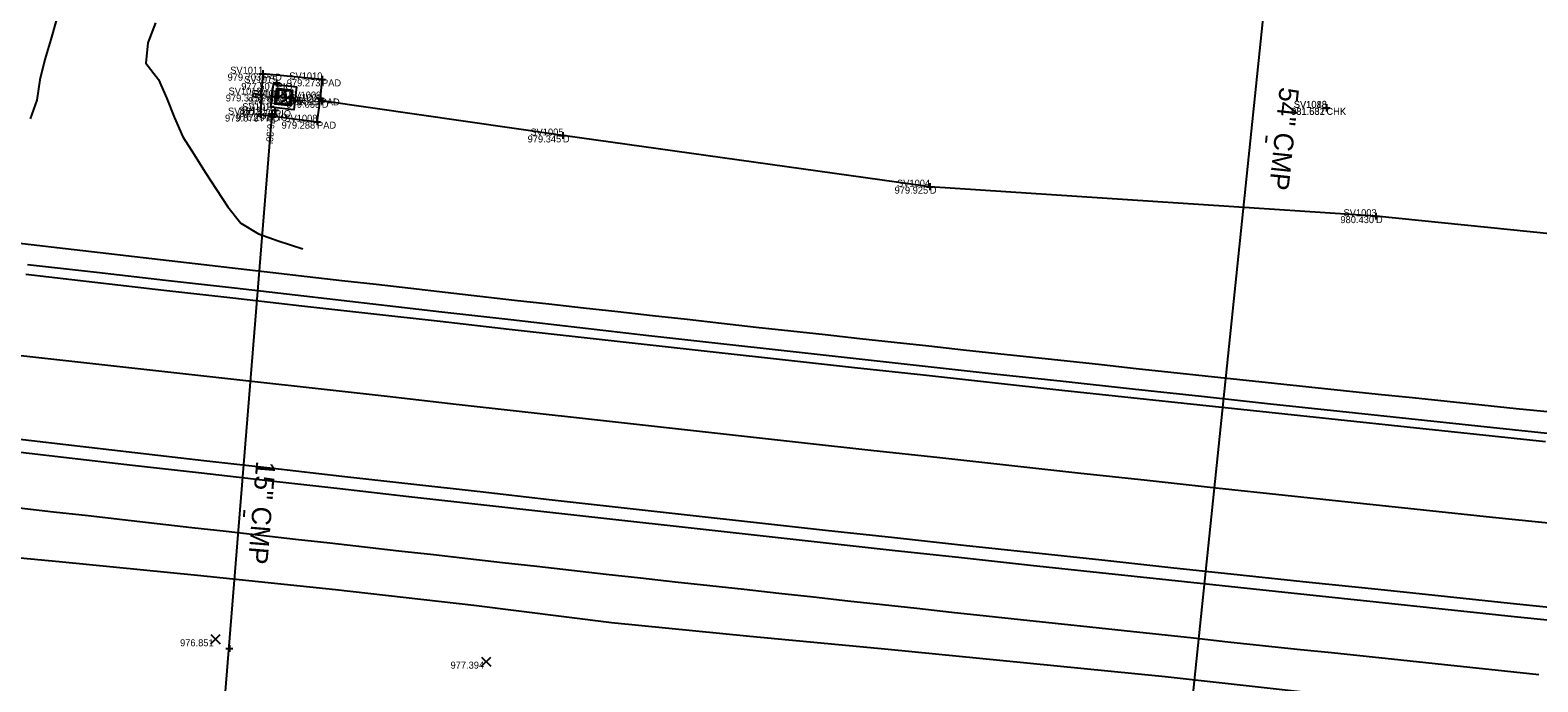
# Model space of a CAD drawing. Extents: x 2065431 to 2068157, y 709104 to 709719.
# Drawn here: x 2067117.5 to 2067334.4, y 709285 to 709378.9 of the extents above; entities that cross this region are included whole.
import ezdxf

# ---------------------------------------------------------------- set-up
doc = ezdxf.new("R2010")
doc.units = 0
for name, color, linetype in [('_CIVIL_CONSTRUCTION', 7, 'Continuous'), ('DR_X_Storm_Sewer', 7, 'Continuous'), ('DR_X_Text', 7, 'Continuous'), ('DT_X_Break_Line', 7, 'Continuous'), ('PM_X_Edge_Line', 7, 'Continuous'), ('PM_X_Lane_Line', 7, 'Continuous'), ('PV_X_EOP', 7, 'Continuous'), ('PV_X_Shoulder_Rumble_Strip', 7, 'Continuous'), ('RD_X_Concrete_Pad', 7, 'Continuous'), ('RS_Raster1', 7, 'Continuous'), ('RW_X_CL', 7, 'Continuous'), ('RW_X_CL_100_Bearings', 7, 'Continuous'), ('RW_X_Fee_WL', 7, 'Continuous'), ('SC_Scratch1', 7, 'Continuous'), ('SV_X_Mon_Cells_Found', 7, 'Continuous'), ('SV_X_Text_Comment', 7, 'Continuous'), ('SV_X_Text_Elevation', 7, 'Continuous'), ('SV_X_Text_Name', 7, 'Continuous')]:
    doc.layers.add(name, color=color, linetype=linetype)

msp = doc.modelspace()

# ---------------------------------------------------------------- linework, layer by layer
at = {"layer": '_CIVIL_CONSTRUCTION'}
for p, q in [((2067152.45, 709371.25), (2067153.45, 709371.25)), ((2067152.95, 709371.75), (2067152.95, 709370.75)), ((2067152.95, 709371.25), (2067152.95, 709371.25)), ((2067151.75, 709366.82), (2067152.75, 709366.82)), ((2067152.21, 709367.33), (2067153.21, 709367.33)), ((2067152.25, 709367.32), (2067152.25, 709366.32)), ((2067152.25, 709366.82), (2067152.25, 709366.82)), ((2067152.71, 709367.83), (2067152.71, 709366.83)), ((2067152.71, 709367.33), (2067152.71, 709367.33))]:
    msp.add_line(p, q, dxfattribs=at)
at = {"layer": 'DR_X_Storm_Sewer'}
for p, q in [((2067313.91, 709564.11), (2067272.26, 709162.87)), ((2067152.25, 709366.82), (2067142.97, 709251.99))]:
    msp.add_line(p, q, dxfattribs=at)
at = {"layer": 'DR_X_Text'}
for p, q in [((2067295.33, 709362.67), (2067295.43, 709363.63)), ((2067148.26, 709308.77), (2067148.34, 709309.74))]:
    msp.add_line(p, q, dxfattribs=at)
at = {"layer": 'DT_X_Break_Line'}
msp.add_lwpolyline([(2067101.73, 709304.2), (2067121.64, 709302.33), (2067141.54, 709300.39), (2067161.43, 709298.3), (2067181.3, 709296.03), (2067201.15, 709293.56), (2067221.05, 709291.6), (2067240.96, 709289.7), (2067260.87, 709287.74), (2067280.77, 709285.77), (2067300.65, 709283.57), (2067320.49, 709281.09), (2067340.37, 709278.88), (2067360.28, 709276.99), (2067380.18, 709275.07), (2067400.09, 709273.09), (2067419.99, 709271.15), (2067439.91, 709269.35), (2067459.83, 709267.56), (2067469.03, 709266.73)], dxfattribs=at)
at = {"layer": 'PM_X_Edge_Line'}
for points in [[(2067116.84, 709343.69), (2067126.78, 709342.56), (2067136.71, 709341.42), (2067146.65, 709340.29), (2067156.58, 709339.16), (2067166.52, 709338.04), (2067176.46, 709336.92), (2067186.39, 709335.8), (2067196.33, 709334.69), (2067206.27, 709333.58), (2067216.21, 709332.48), (2067226.15, 709331.38), (2067236.09, 709330.29), (2067246.03, 709329.2), (2067255.97, 709328.11), (2067265.91, 709327.03), (2067275.85, 709325.96), (2067285.8, 709324.89), (2067295.74, 709323.82), (2067305.68, 709322.76), (2067315.63, 709321.71), (2067325.57, 709320.65), (2067335.52, 709319.61)], [(2067112.67, 709320.32), (2067122.61, 709319.18), (2067132.54, 709318.04), (2067142.48, 709316.9), (2067152.41, 709315.77), (2067162.35, 709314.64), (2067172.28, 709313.52), (2067182.22, 709312.4), (2067192.16, 709311.28), (2067202.1, 709310.17), (2067212.04, 709309.07), (2067221.98, 709307.97), (2067231.92, 709306.87), (2067241.86, 709305.79), (2067251.8, 709304.7), (2067261.74, 709303.63), (2067271.68, 709302.56), (2067281.62, 709301.49), (2067291.57, 709300.43), (2067301.51, 709299.37), (2067311.46, 709298.33), (2067321.4, 709297.28), (2067331.35, 709296.24), (2067341.29, 709295.21)]]:
    msp.add_lwpolyline(points, dxfattribs=at)
at = {"layer": 'PM_X_Lane_Line'}
msp.add_lwpolyline([(2067109.22, 709332.79), (2067119.15, 709331.67), (2067129.09, 709330.56), (2067139.03, 709329.45), (2067148.97, 709328.35), (2067158.91, 709327.25), (2067168.85, 709326.13), (2067178.78, 709325.01), (2067188.72, 709323.89), (2067198.66, 709322.78), (2067208.6, 709321.67), (2067218.54, 709320.57), (2067228.48, 709319.47), (2067238.42, 709318.38), (2067248.36, 709317.29), (2067258.3, 709316.2), (2067268.24, 709315.12), (2067278.18, 709314.04), (2067288.12, 709312.96), (2067298.06, 709311.89), (2067308.01, 709310.83), (2067317.95, 709309.77), (2067327.9, 709308.73), (2067337.84, 709307.7)], dxfattribs=at)
at = {"layer": 'PV_X_EOP'}
for points in [[(2067115.24, 709417.59), (2067117.83, 709416.08), (2067120.3, 709414.41), (2067122.45, 709412.31), (2067123.73, 709409.68), (2067124.59, 709406.81), (2067125.06, 709403.85), (2067125.25, 709400.86), (2067125.25, 709397.86), (2067124.99, 709394.88), (2067124.49, 709391.92), (2067123.95, 709388.98), (2067123.07, 709386.11), (2067122.18, 709383.25), (2067121.29, 709380.38), (2067120.45, 709377.5), (2067119.6, 709374.62), (2067118.87, 709371.71), (2067118.45, 709368.75), (2067117.47, 709366.07)], [(2067135.52, 709379.9), (2067134.43, 709377.04), (2067134.12, 709374.09), (2067135.94, 709371.76), (2067137.15, 709369.02), (2067138.27, 709366.23), (2067139.47, 709363.49), (2067141.08, 709360.95), (2067142.68, 709358.42), (2067144.29, 709355.88), (2067145.95, 709353.39), (2067147.79, 709351.07), (2067150.36, 709349.51), (2067153.17, 709348.49), (2067156.71, 709347.34)], [(2067112.65, 709348.55), (2067117.61, 709347.97), (2067122.58, 709347.4), (2067127.55, 709346.82), (2067132.51, 709346.25), (2067137.48, 709345.68), (2067142.45, 709345.1), (2067147.41, 709344.53), (2067152.38, 709343.96), (2067157.35, 709343.39), (2067162.32, 709342.82), (2067167.28, 709342.25), (2067172.25, 709341.69), (2067177.22, 709341.12), (2067182.19, 709340.56), (2067187.16, 709339.99), (2067192.12, 709339.43), (2067197.09, 709338.87), (2067202.06, 709338.32), (2067207.03, 709337.76), (2067212, 709337.21), (2067216.97, 709336.65), (2067221.94, 709336.1), (2067226.91, 709335.55), (2067231.88, 709335), (2067236.85, 709334.46), (2067241.82, 709333.91), (2067246.79, 709333.37), (2067251.76, 709332.83), (2067256.73, 709332.29), (2067261.7, 709331.75), (2067266.67, 709331.21), (2067271.64, 709330.68), (2067276.62, 709330.14), (2067281.59, 709329.61), (2067286.56, 709329.08), (2067291.53, 709328.55), (2067296.5, 709328.03), (2067301.48, 709327.5), (2067306.45, 709326.98), (2067311.42, 709326.45), (2067316.39, 709325.93), (2067321.37, 709325.41), (2067326.34, 709324.9), (2067331.31, 709324.38), (2067336.29, 709323.87)], [(2067115.89, 709310.08), (2067120.86, 709309.51), (2067125.83, 709308.95), (2067130.79, 709308.38), (2067135.76, 709307.82), (2067140.73, 709307.25), (2067145.7, 709306.69), (2067150.67, 709306.13), (2067155.64, 709305.57), (2067160.6, 709305), (2067165.57, 709304.44), (2067170.54, 709303.88), (2067175.51, 709303.32), (2067180.48, 709302.76), (2067185.45, 709302.2), (2067190.41, 709301.64), (2067195.38, 709301.09), (2067200.35, 709300.53), (2067205.32, 709299.98), (2067210.29, 709299.43), (2067215.26, 709298.88), (2067220.23, 709298.33), (2067225.2, 709297.78), (2067230.17, 709297.23), (2067235.14, 709296.69), (2067240.11, 709296.15), (2067245.08, 709295.6), (2067250.05, 709295.06), (2067255.02, 709294.52), (2067259.99, 709293.99), (2067264.97, 709293.45), (2067269.94, 709292.91), (2067274.91, 709292.38), (2067279.88, 709291.85), (2067284.85, 709291.32), (2067289.82, 709290.79), (2067294.8, 709290.26), (2067299.77, 709289.73), (2067304.74, 709289.21), (2067309.71, 709288.68), (2067314.69, 709288.16), (2067319.66, 709287.64), (2067324.63, 709287.12), (2067329.6, 709286.6), (2067334.58, 709286.08)]]:
    msp.add_lwpolyline(points, dxfattribs=at)
at = {"layer": 'PV_X_Shoulder_Rumble_Strip'}
for points in [[(2067117.09, 709345.12), (2067127.03, 709343.99), (2067136.96, 709342.85), (2067146.9, 709341.72), (2067156.84, 709340.59), (2067166.77, 709339.44), (2067176.7, 709338.3), (2067186.64, 709337.16), (2067196.58, 709336.03), (2067206.51, 709334.9), (2067216.45, 709333.78), (2067226.39, 709332.67), (2067236.33, 709331.56), (2067246.26, 709330.46), (2067256.2, 709329.36), (2067266.14, 709328.28), (2067276.09, 709327.19), (2067286.03, 709326.12), (2067295.97, 709325.04), (2067305.91, 709323.98), (2067315.86, 709322.92), (2067325.8, 709321.87), (2067335.75, 709320.82)], [(2067112.35, 709318.51), (2067122.28, 709317.37), (2067132.22, 709316.23), (2067142.15, 709315.09), (2067152.09, 709313.96), (2067162.02, 709312.83), (2067171.96, 709311.71), (2067181.9, 709310.59), (2067191.84, 709309.47), (2067201.77, 709308.36), (2067211.71, 709307.26), (2067221.65, 709306.16), (2067231.59, 709305.06), (2067241.53, 709303.98), (2067251.47, 709302.89), (2067261.42, 709301.82), (2067271.36, 709300.75), (2067281.3, 709299.68), (2067291.25, 709298.62), (2067301.19, 709297.56), (2067311.13, 709296.52), (2067321.08, 709295.47), (2067331.03, 709294.43), (2067340.97, 709293.4)]]:
    msp.add_lwpolyline(points, dxfattribs=at)
at = {"layer": 'RD_X_Concrete_Pad'}
msp.add_line((2067150.62, 709366.69), (2067158.76, 709365.67), dxfattribs=at)
msp.add_lwpolyline([(2067158.76, 709365.67), (2067159.28, 709369.01), (2067159.48, 709371.76), (2067150.95, 709372.58), (2067150.7, 709369.58), (2067150.62, 709366.69)], dxfattribs=at)
at = {"layer": 'RS_Raster1'}
for p, q in [((2067150.45, 709372.58), (2067151.45, 709372.58)), ((2067150.95, 709373.08), (2067150.95, 709372.08)), ((2067150.95, 709372.58), (2067150.95, 709372.58)), ((2067158.98, 709371.76), (2067159.98, 709371.76)), ((2067159.48, 709372.26), (2067159.48, 709371.26)), ((2067159.48, 709371.76), (2067159.48, 709371.76)), ((2067150.2, 709369.58), (2067151.2, 709369.58)), ((2067150.7, 709370.08), (2067150.7, 709369.08)), ((2067150.7, 709369.58), (2067150.7, 709369.58)), ((2067153.72, 709369.15), (2067154.72, 709369.15)), ((2067153.75, 709369.21), (2067154.75, 709369.21)), ((2067154.22, 709369.65), (2067154.22, 709368.65)), ((2067154.22, 709369.15), (2067154.22, 709369.15)), ((2067154.25, 709369.71), (2067154.25, 709368.71)), ((2067154.25, 709369.21), (2067154.25, 709369.21)), ((2067158.78, 709369.01), (2067159.78, 709369.01)), ((2067158.94, 709368.67), (2067159.94, 709368.67)), ((2067159.28, 709369.51), (2067159.28, 709368.51)), ((2067159.28, 709369.01), (2067159.28, 709369.01)), ((2067159.44, 709369.17), (2067159.44, 709368.17)), ((2067159.44, 709368.67), (2067159.44, 709368.67)), ((2067303.99, 709368.17), (2067303.99, 709367.17)), ((2067150.12, 709366.69), (2067151.12, 709366.69)), ((2067150.62, 709367.19), (2067150.62, 709366.19)), ((2067150.62, 709366.69), (2067150.62, 709366.69)), ((2067158.76, 709366.17), (2067158.76, 709365.17)), ((2067303.49, 709367.67), (2067304.49, 709367.67)), ((2067303.5, 709367.64), (2067304.5, 709367.64)), ((2067303.99, 709367.67), (2067303.99, 709367.67)), ((2067304, 709368.14), (2067304, 709367.14)), ((2067304, 709367.64), (2067304, 709367.64)), ((2067158.26, 709365.67), (2067159.26, 709365.67)), ((2067158.76, 709365.67), (2067158.76, 709365.67)), ((2067194.13, 709364.18), (2067194.13, 709363.18)), ((2067193.63, 709363.68), (2067194.63, 709363.68)), ((2067194.13, 709363.68), (2067194.13, 709363.68)), ((2067246.43, 709356.31), (2067247.43, 709356.31)), ((2067246.93, 709356.81), (2067246.93, 709355.81)), ((2067246.93, 709356.31), (2067246.93, 709356.31)), ((2067310.62, 709352.06), (2067311.62, 709352.06)), ((2067311.12, 709352.56), (2067311.12, 709351.56)), ((2067311.12, 709352.06), (2067311.12, 709352.06)), ((2067146.16, 709290.31), (2067146.16, 709289.31)), ((2067145.66, 709289.81), (2067146.66, 709289.81)), ((2067146.16, 709289.81), (2067146.16, 709289.81))]:
    msp.add_line(p, q, dxfattribs=at)
at = {"layer": 'RW_X_CL'}
for p, q in [((2067154.16, 709370.87), (2067154.16, 709370.87)), ((2067152.97, 709369.33), (2067152.97, 709369.33)), ((2067153.85, 709368.22), (2067153.85, 709368.22)), ((2067153.96, 709369.21), (2067153.96, 709369.21)), ((2067153.96, 709369.21), (2067153.96, 709369.21)), ((2067153.96, 709369.21), (2067153.96, 709369.21)), ((2067154.08, 709370.21), (2067154.08, 709370.21)), ((2067154.96, 709369.1), (2067154.96, 709369.1)), ((2067153.77, 709367.56), (2067153.77, 709367.56))]:
    msp.add_line(p, q, dxfattribs=at)
at = {"layer": 'RW_X_CL_100_Bearings'}
for p, q in [((2067143.46, 709290.46), (2067144.8, 709291.8)), ((2067143.46, 709291.8), (2067144.8, 709290.46)), ((2067182.43, 709287.25), (2067183.76, 709288.58)), ((2067182.43, 709288.58), (2067183.76, 709287.25))]:
    msp.add_line(p, q, dxfattribs=at)
at = {"layer": 'RW_X_Fee_WL'}
msp.add_lwpolyline([(2067471.85, 709335.31), (2067418.47, 709340.79), (2067365.44, 709346.52), (2067311.12, 709352.06), (2067246.93, 709356.31), (2067194.13, 709363.68), (2067159.44, 709368.67)], dxfattribs=at)
at = {"layer": 'SV_X_Text_Comment'}
for p, q in [((2067152.89, 709369.86), (2067153.58, 709370.41)), ((2067152.76, 709368.74), (2067154.71, 709370.28)), ((2067153.29, 709368.14), (2067155.17, 709369.63)), ((2067154.41, 709368.01), (2067155.04, 709368.5))]:
    msp.add_line(p, q, dxfattribs=at)
for points in [[(2067152.5, 709371.06), (2067155.81, 709370.68), (2067155.43, 709367.37), (2067152.12, 709367.75)], [(2067152.96, 709370.49), (2067155.24, 709370.22), (2067154.97, 709367.94), (2067152.69, 709368.21)], [(2067153.09, 709370.32), (2067155.07, 709370.09), (2067154.84, 709368.11), (2067152.86, 709368.34)]]:
    msp.add_lwpolyline(points, close=True, dxfattribs=at)

# ---------------------------------------------------------------- texts
at = {"layer": 'DR_X_Text'}
for s, rotation, p in [('54" CMP', 264.0747, (2067297.28, 709370.72)), ('15" CMP', 265.3805, (2067150.02, 709316.86))]:
    msp.add_text(s, height=2.8, rotation=rotation, dxfattribs=at).set_placement(p)
at = {"layer": 'SC_Scratch1'}
msp.add_text("976.30'", height=1, rotation=265.3805, dxfattribs=at).set_placement((2067151.76, 709366.87))
at = {"layer": 'SV_X_Mon_Cells_Found'}
for s, p in [('SV1011', (2067146.27, 709372.58)), ('SV1010', (2067154.77, 709371.76)), ('SV1012', (2067146.03, 709369.58)), ('SV1015', (2067148.29, 709371.25)), ('SV1016', (2067148.01, 709367.33)), ('SV1007', (2067149.27, 709369.21)), ('SV1148', (2067149.52, 709369.15)), ('SV1014', (2067149.53, 709369.21)), ('SV1009', (2067154.6, 709369.01)), ('SV1006', (2067154.74, 709368.67)), ('SV1018', (2067299.29, 709367.67)), ('SV1088', (2067299.31, 709367.64)), ('SV1013', (2067145.95, 709366.69)), ('SV1017', (2067147.56, 709366.82)), ('SV1008', (2067154.06, 709365.67)), ('SV1005', (2067189.46, 709363.68)), ('SV1004', (2067242.21, 709356.31)), ('SV1003', (2067306.46, 709352.06))]:
    msp.add_text(s, height=1, dxfattribs=at).set_placement(p)
at = {"layer": 'SV_X_Text_Elevation'}
for s, p in [('PAD', (2067150.95, 709371.58)), ('PIO', (2067152.95, 709370.25)), ('PAD', (2067159.48, 709370.76)), ('PAD', (2067150.7, 709368.58)), ('CBS', (2067153.96, 709368.21)), ('CHK', (2067154.22, 709368.15)), ('CHK', (2067154.25, 709368.21)), ('PAD', (2067159.28, 709368.01)), ('D', (2067159.44, 709367.67)), ('PAD', (2067150.62, 709365.69)), ('PIO', (2067152.25, 709365.82)), ('PIO', (2067152.71, 709366.33)), ('CHK', (2067303.99, 709366.67)), ('CHK', (2067304, 709366.64)), ('PAD', (2067158.76, 709364.67)), ('D', (2067194.13, 709362.68)), ('D', (2067246.93, 709355.31)), ('D', (2067311.12, 709351.06))]:
    msp.add_text(s, height=1, dxfattribs=at).set_placement(p)
at = {"layer": 'SV_X_Text_Name'}
for s, p in [('979.703', (2067145.89, 709371.58)), ('977.507', (2067147.86, 709370.25)), ('979.273', (2067154.41, 709370.76)), ('979.375', (2067145.63, 709368.58)), ('978.968', (2067148.86, 709368.21)), ('978.950', (2067149.14, 709368.21)), ('978.815', (2067149.15, 709368.15)), ('979.095', (2067154.21, 709368.01)), ('979.055', (2067154.37, 709367.67)), ('979.678', (2067145.52, 709365.69)), ('976.297', (2067147.16, 709365.82)), ('977.378', (2067147.61, 709366.33)), ('981.681', (2067298.91, 709366.67)), ('981.532', (2067298.93, 709366.64)), ('979.288', (2067153.66, 709364.67)), ('979.345', (2067189.06, 709362.68)), ('979.925', (2067241.86, 709355.31)), ('980.430', (2067306.01, 709351.06)), ('976.851', (2067139.05, 709290.13)), ('977.394', (2067177.97, 709286.91))]:
    msp.add_text(s, height=1, dxfattribs=at).set_placement(p)

doc.saveas('drawing.dxf')
